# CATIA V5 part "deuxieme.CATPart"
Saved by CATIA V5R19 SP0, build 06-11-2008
Part number: Part1.2
Bounding box of the stored display mesh (mm): x -30 to 30, y -435.613 to 219.055, z -12.333 to 56.576
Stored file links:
  D:\thinkmotion-MPB\Dropbox\CIAO82010_JCF\BELAZOUZ\548-belazouz\deuxieme.CATPart
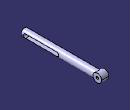
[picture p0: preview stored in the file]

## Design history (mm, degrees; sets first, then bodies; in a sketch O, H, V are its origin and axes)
Body1 (main body)
  Sketch1 on yz-plane, origin (0, 0, 0), H (0, 1, 0), V (0, 0, 1)
    line L1 (164.3871, 20.7358) -> (-435.6129, 20.7358)
    line L2 (164.3871, 20.7358) -> (164.3871, -9.2642)
    line L3 (164.3871, -9.2642) -> (-435.6129, -9.2642)
    line L4 (-435.6129, -9.2642) -> (-435.6129, 20.7358)
    length L1 = 600
    length L2 = 30
    horizontal: L1 H, L3 H
    vertical: L2 V, L4 V
  Shaft1: profile Sketch1, axis Sketch1.L1, angle 360
  Sketch2 on yz-plane, origin (0, 0, 0), H (0, 1, 0), V (0, 0, 1)
    circle A1 centre (184.5966, 22.1176) radius 34.458
  Pad1: profile Sketch2, direction (1, 0, 0), length 30, opposite side length 30
  Sketch3 on start face of Pad1, origin (-30, 192.0296, 21.5755), H (0, 1, 0), V (0, 0, -1)
    point P1 (-7.3891, -1.0058)
  Hole1: placed by Sketch3, at (-30, 184.6405, 22.5814) direction (1, 0, 0), diameter 20, through (limit type 3)
  Sketch4 on yz-plane, origin (0, 0, 0), H (0, 1, 0), V (0, 0, 1)
    construction line L1 (-404.2173, 19.9697) -> (-145.6188, 19.9697)
    line L2 (-404.2173, 35.7358) -> (-145.6188, 35.7358)
    line L3 (-145.6188, 4.2036) -> (-404.2173, 4.2036)
    arc A1 centre (-145.6188, 19.9697) radius 15.7661 from (-145.6188, 35.7358) to (-145.6188, 4.2036) cw
    arc A2 centre (-404.2173, 19.9697) radius 15.7661 from (-404.2173, 4.2036) to (-404.2173, 35.7358) cw
    reference projected line E1 through (0, 20.7358) direction (-1, 0) from axis of face of Shaft1 from Sketch1.L3
    distance L1 L2 = 15.7661
    distance L2 E1 = 15
    horizontal: L1 H
    tangency: A1 L2, A2 L2, A1 L3, A2 L3
  Pocket1: profile Sketch4, direction (1, 0, 0), length 30, opposite side length 36
  Point1: stored without definition
  Line1: type PtDir, RefPoint Point1, Direction edge [face of Pocket1 from Sketch4.L3 | face of Shaft1 from Sketch1.L3], Start 0, End 250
